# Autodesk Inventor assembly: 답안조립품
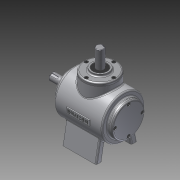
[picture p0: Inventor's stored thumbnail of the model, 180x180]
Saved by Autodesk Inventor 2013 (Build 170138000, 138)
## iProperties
Created: 2015-01
Part Number: 답안조립품
Document SubType Name: Assembly
Designer: Administrator
Author: Administrator
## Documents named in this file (15)
- C:\Documents and Settings\Administrator\바탕 화면\450106V1025\답안조립품.iam
- C:\Documents and Settings\Administrator\바탕 화면\450106V1025\본체.ipt
- C:\Documents and Settings\Administrator\바탕 화면\450106V1025\메인 베벨기어.ipt
- C:\Documents and Settings\Administrator\바탕 화면\450106V1025\메인 축.ipt
- 메인 축.ipt
- C:\Documents and Settings\Administrator\바탕 화면\450106V1025\베어링 6203.ipt
- C:\Documents and Settings\Administrator\바탕 화면\450106V1025\서브 베벨기어.ipt
- C:\Documents and Settings\Administrator\바탕 화면\450106V1025\서브 축.ipt
- 서브 축.ipt
- C:\Documents and Settings\Administrator\바탕 화면\450106V1025\오일실.ipt
- C:\Documents and Settings\Administrator\바탕 화면\450106V1025\커버2.ipt
- C:\Documents and Settings\Administrator\바탕 화면\450106V1025\커버.ipt
- C:\Documents and Settings\Administrator\바탕 화면\450106V1025\키 4x4.ipt
- C:\Documents and Settings\Administrator\바탕 화면\450106V1025\키 5x5.ipt
- C:\Documents and Settings\Administrator\바탕 화면\450106V1025\M4.ipt
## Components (12 placed, 1 different names)
1. M4:1
2. M4:3
3. M4:4
4. M4:5
5. M4:2
6. M4:6
7. M4:7
8. M4:8
9. M4:9
10. M4:10
11. M4:11
12. M4:12
